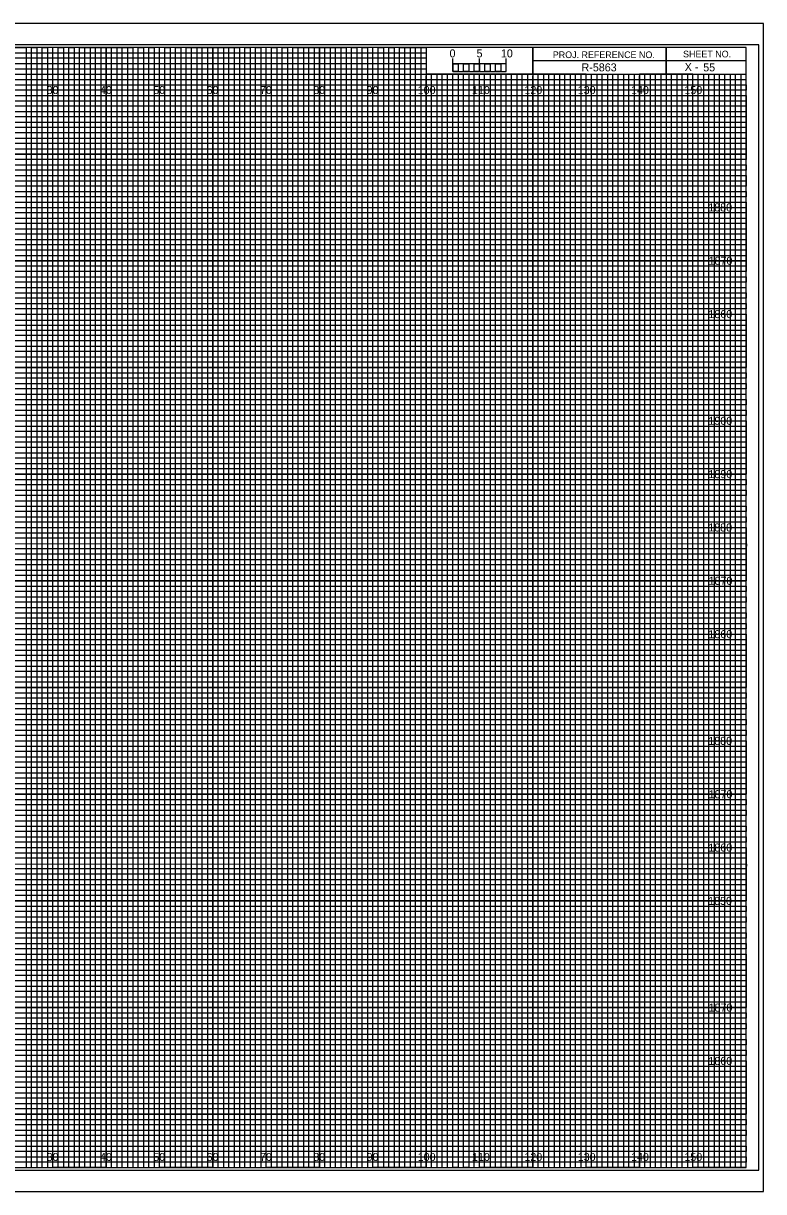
# Model space of a CAD drawing. Extents: x -13 to 323, y -4 to 214.
# Drawn here: x 184.5 to 323.3, y -4.5 to 214.5 of the extents above; entities that cross this region are included whole.
import ezdxf

# ---------------------------------------------------------------- set-up
doc = ezdxf.new("R2010")
doc.units = 0
for name, color, linetype in [('Prop XS Bar Scale Labels', 7, 'Continuous'), ('Prop XS Elevation Labels', 7, 'Continuous'), ('Prop XS Offset Labels', 7, 'Continuous'), ('Prop XS Project Number', 7, 'Continuous'), ('Prop XS Sheet Number', 7, 'Continuous'), ('Sheet Cross Section CELL', 7, 'Continuous'), ('Sheet Cross Section Grid Major CELL', 7, 'Continuous'), ('Sheet Cross Section Grid Middle CELL', 7, 'Continuous'), ('Sheet Cross Section Grid Minor 1 CELL', 7, 'Continuous'), ('Sheet Cross Section Grid Minor 2 CELL', 7, 'Continuous'), ('Sheet Cross Section Scale CELL', 7, 'Continuous'), ('Sheet Cutting Line CELL', 7, 'Continuous'), ('Sheet DOT Grid CELL', 7, 'Continuous'), ('Sheet Plot Border Inside CELL', 7, 'Continuous'), ('Sheet Plot Border Outside CELL', 7, 'Continuous')]:
    doc.layers.add(name, color=color, linetype=linetype)

msp = doc.modelspace()

# ---------------------------------------------------------------- linework, layer by layer
at = {"layer": 'Sheet Cross Section CELL'}
for p, q in [((305, 210), (305, 205)), ((305, 205), (305, 210)), ((280, 207.5), (280, 205)), ((320, 207.49), (280, 207.49)), ((280, 205), (320, 205))]:
    msp.add_line(p, q, dxfattribs=at)
for points in [[(320, 210), (0, 210), (0, 0), (320, 0)], [(280, 210), (260, 210), (260, 205.03), (280, 205.03)], [(320, 210), (280, 210), (280, 205), (320, 205)]]:
    msp.add_lwpolyline(points, close=True, dxfattribs=at)
at = {"layer": 'Sheet Cross Section Grid Major CELL'}
for p, q in [((190, 210), (180, 210)), ((190, 0), (190, 210)), ((210, 210), (200, 210)), ((200, 210), (200, 0)), ((210, 0), (210, 210)), ((230, 210), (220, 210)), ((220, 210), (220, 0)), ((230, 0), (230, 210)), ((250, 210), (240, 210)), ((240, 210), (240, 0)), ((250, 0), (250, 210)), ((260, 210), (260, 0)), ((270, 0), (270, 205)), ((290, 205), (280, 205)), ((280, 205), (280, 0)), ((290, 0), (290, 205)), ((310, 205), (300, 205)), ((300, 205), (300, 0)), ((310, 0), (310, 205)), ((200, 0), (190, 0)), ((220, 0), (210, 0)), ((240, 0), (230, 0)), ((260, 0), (250, 0)), ((280, 0), (270, 0)), ((300, 0), (290, 0)), ((320, 0), (310, 0)), ((320, 0), (320, 0))]:
    msp.add_line(p, q, dxfattribs=at)
for points in [[(0, 200), (320, 200), (320, 190), (0, 190)], [(0, 180), (320, 180), (320, 170), (0, 170)], [(0, 160), (320, 160), (320, 150), (0, 150)], [(0, 140), (320, 140), (320, 130), (0, 130)], [(0, 120), (320, 120), (320, 110), (0, 110)], [(0, 100), (320, 100), (320, 90), (0, 90)], [(0, 80), (320, 80), (320, 70), (0, 70)], [(0, 60), (320, 60), (320, 50), (0, 50)], [(0, 40), (320, 40), (320, 30), (0, 30)], [(0, 20), (320, 20), (320, 10), (0, 10)]]:
    msp.add_lwpolyline(points, dxfattribs=at)
at = {"layer": 'Sheet Cross Section Grid Middle CELL'}
for points in [[(175, 210), (185, 210), (185, 0), (195, 0), (195, 210), (205, 210), (205, 0), (215, 0), (215, 210), (225, 210), (225, 0), (235, 0), (235, 210), (245, 210), (245, 0), (255, 0), (255, 210), (259.93, 210), (260, 210), (260, 205), (264.99, 205), (264.99, 0), (275, 0), (275, 205), (285, 205), (285, 0), (295, 0), (295, 205), (305, 205), (305, 0), (315, 0), (315, 205)], [(0, 205), (275, 205)], [(0, 185), (320, 185), (320, 195), (0, 195)], [(0, 165), (320, 165), (320, 175), (0, 175)], [(0, 145), (320, 145), (320, 155), (0, 155)], [(0, 125), (320, 125), (320, 135), (0, 135)], [(0, 105), (320, 105), (320, 115), (0, 115)], [(0, 85), (320, 85), (320, 95), (0, 95)], [(0, 65), (320, 65), (320, 75), (0, 75)], [(0, 45), (320, 45), (320, 55), (0, 55)], [(0, 25), (320, 25), (320, 35), (0, 35)], [(0, 5), (320, 5), (320, 15), (0, 15)]]:
    msp.add_lwpolyline(points, dxfattribs=at)
at = {"layer": 'Sheet Cross Section Grid Minor 1 CELL'}
for p, q in [((0, 209), (260, 209)), ((260, 209), (260, 207.98)), ((260, 207.98), (0, 207.98)), ((0, 207), (260, 207)), ((260, 205.89), (0, 205.89)), ((260, 207), (260, 205.89)), ((0, 204), (320, 204))]:
    msp.add_line(p, q, dxfattribs=at)
for points in [[(0, 203), (270, 203), (320, 203), (320, 202), (0, 202)], [(0, 201), (320, 201), (320, 199), (0, 199)], [(0, 198), (320, 198), (320, 197), (0, 196.98)], [(0, 196), (320, 196), (320, 194), (0, 194)], [(0, 193), (320, 193), (320, 192), (0, 192)], [(0, 191), (320, 191), (320, 189), (0, 189)], [(0, 188), (320, 188), (320, 187), (0, 187)], [(0, 186), (320, 186), (320, 184), (0, 184)], [(0, 183), (320, 183), (320, 182), (0, 182)], [(0, 181), (320, 181), (320, 179), (0, 179)], [(0, 178), (320, 178), (320, 177), (0, 177)], [(0, 176), (320, 176), (320, 173.95), (320, 173), (320, 172), (0, 172)], [(0, 174), (320, 174), (320, 173), (0, 173)], [(0, 171), (320, 171), (320, 169), (0, 169.03)], [(0, 169.03), (320, 169), (320, 168), (0, 168)], [(0, 167), (320, 167), (320, 166), (0, 166)], [(0, 164), (320, 164), (320, 163), (0, 163)], [(0, 162), (320, 162), (320, 161), (0, 161)], [(-0.07, 158.89), (320, 158.89), (320, 157.88), (-0.07, 157.88)], [(0, 157), (320, 157), (320, 156), (0, 156)], [(0, 154), (320, 154), (320, 153), (0, 153)], [(0, 152), (320, 152), (320, 151), (0, 151)], [(0, 149), (320, 149), (320, 148), (0, 148)], [(0, 147), (320, 147), (320, 146), (0, 146)], [(0, 144), (320, 144), (320, 143), (0, 143)], [(0, 142), (320, 142), (320, 141), (0, 141)], [(0, 139), (320, 139), (319.99, 137.98), (0, 138)], [(0, 137), (320, 137), (320, 136), (0, 136)], [(0, 134), (320, 134), (320, 133), (0, 133)], [(0, 132), (320, 132), (320, 131), (0, 131)], [(0, 129), (320, 129), (320, 128), (0, 128)], [(0, 127), (320, 127), (320, 126), (0, 126)], [(0, 124), (320, 124), (320, 123), (0, 123)], [(0, 122), (320, 122), (320, 121), (0, 121)], [(0, 119), (320, 119), (320, 118), (0, 118)], [(0, 116.99), (320.07, 116.91), (320, 116), (0, 116)], [(0, 114), (320, 114), (320, 113), (0, 113)], [(0, 112), (320, 112), (320, 111), (0, 111)], [(0, 109), (320, 109), (320, 108), (0, 108)], [(0, 107), (320, 107), (320, 106), (0, 106)], [(0, 104), (320, 104), (320, 103), (0, 103)], [(0, 102), (320, 102), (320, 101), (0, 101)], [(0, 99), (320, 99), (320, 98), (0, 98)], [(0, 97), (320, 97), (320, 96), (0, 96)], [(0, 94), (320, 94), (320, 93), (0, 93)], [(0, 92), (320, 92), (320, 91), (0, 91)], [(0, 89), (320, 89), (320, 88), (0, 88)], [(0, 87), (320, 87), (320, 86), (0, 86)], [(0, 84), (320, 84), (320, 83), (0, 83)], [(0, 82), (320, 82), (320, 81), (0, 81)], [(0, 79), (320, 79), (319.99, 77.98), (0, 78)], [(0, 77), (320, 77), (320, 76), (0, 76)], [(0, 74), (320, 74), (320, 73), (0, 73)], [(0, 72), (320, 72), (320, 71), (0, 71)], [(0, 69), (320, 69), (320, 68), (0, 68)], [(0, 67), (320, 67), (320, 66), (0, 66)], [(0, 64), (320, 64), (320, 63), (0, 63)], [(0, 62), (320, 62), (320, 61), (0, 61)], [(0, 59), (320, 59), (320, 58), (0, 58)], [(0, 56.99), (320.07, 56.91), (320, 56), (0, 56)], [(0, 54), (320, 54), (320, 53), (0, 53)], [(0, 52), (320, 52), (320, 51), (0, 51)], [(0, 49), (320, 49), (320, 48), (0, 48)], [(0, 47), (320, 47), (320, 46), (0, 46)], [(0, 44), (320, 44), (320, 43), (0, 43)], [(0, 42), (320, 42), (320, 41), (0, 41)], [(0, 39), (320, 39), (320, 38), (0, 38)], [(0, 37), (320, 37), (320, 36), (0, 36)], [(0, 34), (320, 34), (320, 33), (0, 33)], [(0, 32), (320, 32), (320, 31), (0, 31)], [(0, 29), (320, 29), (320, 28), (0, 28)], [(0, 27), (320, 27), (320, 26), (0, 26)], [(0, 24), (320, 24), (320, 23), (0, 23)], [(0, 22), (320, 22), (320, 21), (0, 21)], [(0, 19), (320, 19), (320, 18), (0, 18)], [(0, 17), (320, 17), (320, 16), (0, 16)], [(0, 14), (320, 14), (320, 13), (0, 13)], [(0, 12), (320, 12), (320, 11), (0, 11)], [(0, 9), (320, 9), (320, 8), (0, 8)], [(0, 7), (320, 7), (320, 6), (0, 6)], [(0, 4), (320, 4), (320, 3), (0, 3)], [(0, 2), (320, 2), (320, 1), (0, 1)]]:
    msp.add_lwpolyline(points, dxfattribs=at)
at = {"layer": 'Sheet Cross Section Grid Minor 2 CELL'}
for p, q in [((267, 205), (266.01, 205)), ((266.01, 205), (266.01, 0)), ((267, 0), (267, 205)), ((269, 205), (268, 205)), ((268, 205), (268, 0)), ((269, 0), (269, 205)), ((266.01, 0), (265, 0)), ((268, 0), (267, 0))]:
    msp.add_line(p, q, dxfattribs=at)
for points in [[(185, 0), (186, 0), (186, 210), (187, 210), (187, 0)], [(187, 0), (188, 0), (188, 210), (189, 210), (189, 0)], [(190, 0), (191, 0), (191, 210), (192, 210), (192, 0)], [(192, 0), (193, 0), (193, 210), (194, 210), (194, 0)], [(195, 0), (196, 0), (196, 210), (197, 210), (197, 0)], [(197, 0), (198, 0), (198, 210), (199, 210), (199, 0)], [(200, 0), (201, 0), (201, 210), (202, 210), (202, 0)], [(202, 0), (203, 0), (203, 210), (204, 210), (204, 0)], [(205, 0), (206, 0), (206, 210), (207, 210), (207, 0)], [(207, 0), (208, 0), (208, 210), (209, 210), (209, 0)], [(210, 0), (211, 0), (211, 210), (212, 210), (212, 0)], [(212, 0), (213, 0), (213, 210), (214, 210), (214, 0)], [(215, 0), (216, 0), (216, 210), (217, 210), (217, 0)], [(217, 0), (218, 0), (218, 210), (219, 210), (219, 0)], [(220, 0), (221, 0), (221, 210), (222, 210), (222, 0)], [(222, 0), (223, 0), (223, 210), (224, 210), (224, 0)], [(225, 0), (226, 0), (226, 210), (227, 210), (227, 0)], [(227, 0), (228, 0), (228, 210), (229, 210), (229, 0)], [(230, 0), (231, 0), (231, 210), (232, 210), (232, 0)], [(232, 0), (233, 0), (233, 210), (234, 210), (234, 0)], [(235, 0), (236, 0), (236, 210), (237, 210), (237, 0)], [(237, 0), (238, 0), (238, 210), (239, 210), (239, 0)], [(240, 0), (241, 0), (241, 210), (242, 210), (242, 0)], [(242, 0), (243, 0), (243, 210), (244, 210), (244, 0)], [(245, 0), (246, 0), (246, 210), (247, 210), (247, 0)], [(247, 0), (248, 0), (248, 210), (249, 210), (249, 0)], [(250, 0), (251, 0), (251, 210), (252, 210), (252, 0)], [(252, 0), (253, 0), (253, 210), (254, 210), (254, 0)], [(255, 0), (256, 0), (256, 210), (257, 210), (257, 0)], [(257, 0), (258, 0), (258, 210), (259, 210), (259, 0)], [(260, 0), (261, 0), (261, 205), (262.02, 205), (262.02, 0)], [(262, 0), (263, 0), (263, 205), (263.99, 205), (263.99, 0)], [(270, 0), (270.98, 0), (270.98, 205), (272, 205), (272, 0)], [(272, 0), (273, 0), (273, 205), (274.05, 205), (274.05, 0)], [(275, 0), (276, 0), (276, 205), (277, 205), (277, 0)], [(277, 0), (278, 0), (278, 205), (279, 205), (279, 0)], [(280, 0), (281, 0), (281, 205), (282, 205), (282, 0)], [(282, 0), (283, 0), (283, 205), (284, 205), (284, 0)], [(285, 0), (286, 0), (286, 205), (287, 205), (287, 0)], [(287, 0), (288, 0), (288, 205), (289, 205), (289, 0)], [(290, 0), (291, 0), (291, 205), (292, 205), (292, 0)], [(292, 0), (293, 0), (293, 205), (294, 205), (294, 0)], [(295, 0), (296, 0), (296, 205), (297, 205), (297, 0)], [(297, 0), (298, 0), (298, 205), (299, 205), (299, 0)], [(300, 0), (301, 0), (301, 205), (302, 205), (302, 0)], [(302, 0), (303, 0), (303, 205), (304, 205), (304, 0)], [(305, 0), (306, 0), (306, 205), (307, 205), (307, 0)], [(307, 0), (308, 0), (308, 205), (309, 205), (309, 0)], [(310, 0), (311, 0), (311, 205), (312, 205), (312, 0)], [(312, 0), (313, 0), (313, 205), (314, 205), (314, 0)], [(315, 0), (316, 0), (316, 205), (317, 205), (317, 0)], [(317, 0), (318, 0), (318, 205), (319, 205), (319, 0)]]:
    msp.add_lwpolyline(points, dxfattribs=at)
at = {"layer": 'Sheet Cross Section Scale CELL'}
for p, q in [((265, 205.49), (265, 207.9)), ((265, 206.9), (265, 207.9)), ((270, 205.49), (270, 207.9)), ((275, 205.49), (275, 207.9)), ((275, 206.9), (275, 207.9))]:
    msp.add_line(p, q, dxfattribs=at)
for points in [[(275, 206.9), (265, 206.9), (265, 205.49), (275, 205.49)], [(265, 206.9), (266, 206.9), (266, 205.49), (265, 205.49)], [(267, 206.9), (268, 206.9), (268, 205.49), (267, 205.49)], [(269, 206.9), (270, 206.9), (270, 205.49), (269, 205.49)], [(271, 206.9), (272, 206.9), (272, 205.49), (271, 205.49)], [(273, 206.9), (274, 206.9), (274, 205.49), (273, 205.49)]]:
    msp.add_lwpolyline(points, close=True, dxfattribs=at)
at = {"layer": 'Sheet Cutting Line CELL'}
for p, q in [((323.3, 214.5), (-13.4, 214.5)), ((-13.4, -4.5), (323.3, -4.5))]:
    msp.add_line(p, q, dxfattribs=at)
at = {"layer": 'Sheet DOT Grid CELL'}
for p, q in [((190, 0), (190, 210)), ((200, 0), (200, 210)), ((210, 0), (210, 210)), ((220, 0), (220, 210)), ((230, 0), (230, 210)), ((240, 0), (240, 210)), ((250, 0), (250, 210)), ((260, 0), (260, 204.69)), ((270, 0), (270, 204.69)), ((280, 0), (280, 204.69)), ((290, 0), (290, 204.69)), ((300, 0), (300, 204.69)), ((310, 0), (310, 204.69)), ((0, 200), (320, 200)), ((0, 190), (320, 190)), ((0, 180), (320, 180)), ((0, 170), (320, 170)), ((0, 160), (320, 160)), ((0, 150), (320, 150)), ((0, 140), (320, 140)), ((0, 130), (320, 130)), ((0, 120), (320, 120)), ((0, 110), (320, 110)), ((0, 100), (320, 100)), ((0, 90), (320, 90)), ((0, 80), (320, 80)), ((0, 70), (320, 70)), ((0, 60), (320, 60)), ((0, 50), (320, 50)), ((0, 40), (320, 40)), ((0, 30), (320, 30)), ((0, 20), (320, 20)), ((0, 10), (320, 10))]:
    msp.add_line(p, q, dxfattribs=at)
at = {"layer": 'Sheet Plot Border Inside CELL'}
msp.add_lwpolyline([(-10.8, -0.5), (322.4, -0.5), (322.4, 210.5), (-10.8, 210.5)], close=True, dxfattribs=at)
at = {"layer": 'Sheet Plot Border Outside CELL'}
msp.add_lwpolyline([(-13.4, -4.5), (323.3, -4.5), (323.3, 214.5), (-13.4, 214.5)], close=True, dxfattribs=at)

# ---------------------------------------------------------------- texts
at = {"layer": 'Prop XS Bar Scale Labels'}
for s, p in [('5', (269.47, 208.12)), ('10', (274.04, 208.12))]:
    msp.add_text(s, height=1.5, dxfattribs=at).set_placement(p)
at = {"layer": 'Prop XS Elevation Labels'}
for s, p in [('1880', (312.92, 179.25)), ('1870', (312.98, 169.25)), ('1860', (312.95, 159.25)), ('1900', (312.95, 139.25)), ('1890', (312.95, 129.25)), ('1880', (312.92, 119.25)), ('1870', (312.98, 109.25)), ('1860', (312.95, 99.25)), ('1880', (312.92, 79.25)), ('1870', (312.98, 69.25)), ('1860', (312.95, 59.25)), ('1850', (312.9, 49.25)), ('1870', (312.98, 29.25)), ('1860', (312.95, 19.25))]:
    msp.add_text(s, height=1.5, dxfattribs=at).set_placement(p)
at = {"layer": 'Prop XS Offset Labels'}
for s, p in [('30', (188.86, 201.25)), ('40', (198.86, 201.25)), ('50', (208.86, 201.25)), ('60', (218.86, 201.25)), ('70', (228.86, 201.25)), ('80', (238.86, 201.25)), ('90', (248.86, 201.25)), ('100', (258.44, 201.25)), ('110', (268.62, 201.25)), ('120', (278.44, 201.25)), ('130', (288.44, 201.25)), ('140', (298.44, 201.25)), ('150', (308.44, 201.25)), ('30', (188.86, 1.25)), ('40', (198.86, 1.25)), ('50', (208.86, 1.25)), ('60', (218.86, 1.25)), ('70', (228.86, 1.25)), ('80', (238.86, 1.25)), ('90', (248.86, 1.25)), ('100', (258.44, 1.25)), ('110', (268.62, 1.25)), ('120', (278.44, 1.25)), ('130', (288.44, 1.25)), ('140', (298.44, 1.25)), ('150', (308.44, 1.25))]:
    msp.add_text(s, height=1.5, dxfattribs=at).set_placement(p)
at = {"layer": 'Prop XS Project Number'}
msp.add_text('R-5863', height=1.5, dxfattribs=at).set_placement((289.16, 205.5))
at = {"layer": 'Prop XS Sheet Number'}
msp.add_text('55', height=1.5, dxfattribs=at).set_placement((311.97, 205.5))
at = {"layer": 'Sheet Cross Section CELL'}
for s, height, p in [('PROJ. REFERENCE NO.', 1.25, (283.77, 207.99)), ('SHEET NO.', 1.25, (308.19, 208.12)), ('X -    ', 1.5, (308.5, 205.58))]:
    msp.add_text(s, height=height, dxfattribs=at).set_placement(p)
at = {"layer": 'Sheet Cross Section Scale CELL'}
msp.add_text('0', height=1.5, dxfattribs=at).set_placement((264.41, 208.12))

doc.saveas('drawing.dxf')
